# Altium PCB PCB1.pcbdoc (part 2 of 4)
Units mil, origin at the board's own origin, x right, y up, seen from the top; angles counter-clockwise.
Board outline 6180 x 7065 mil, 2 copper layers (Top Layer, Bottom Layer); 471 components, 245 nets, 1464 pads, 505 vias.
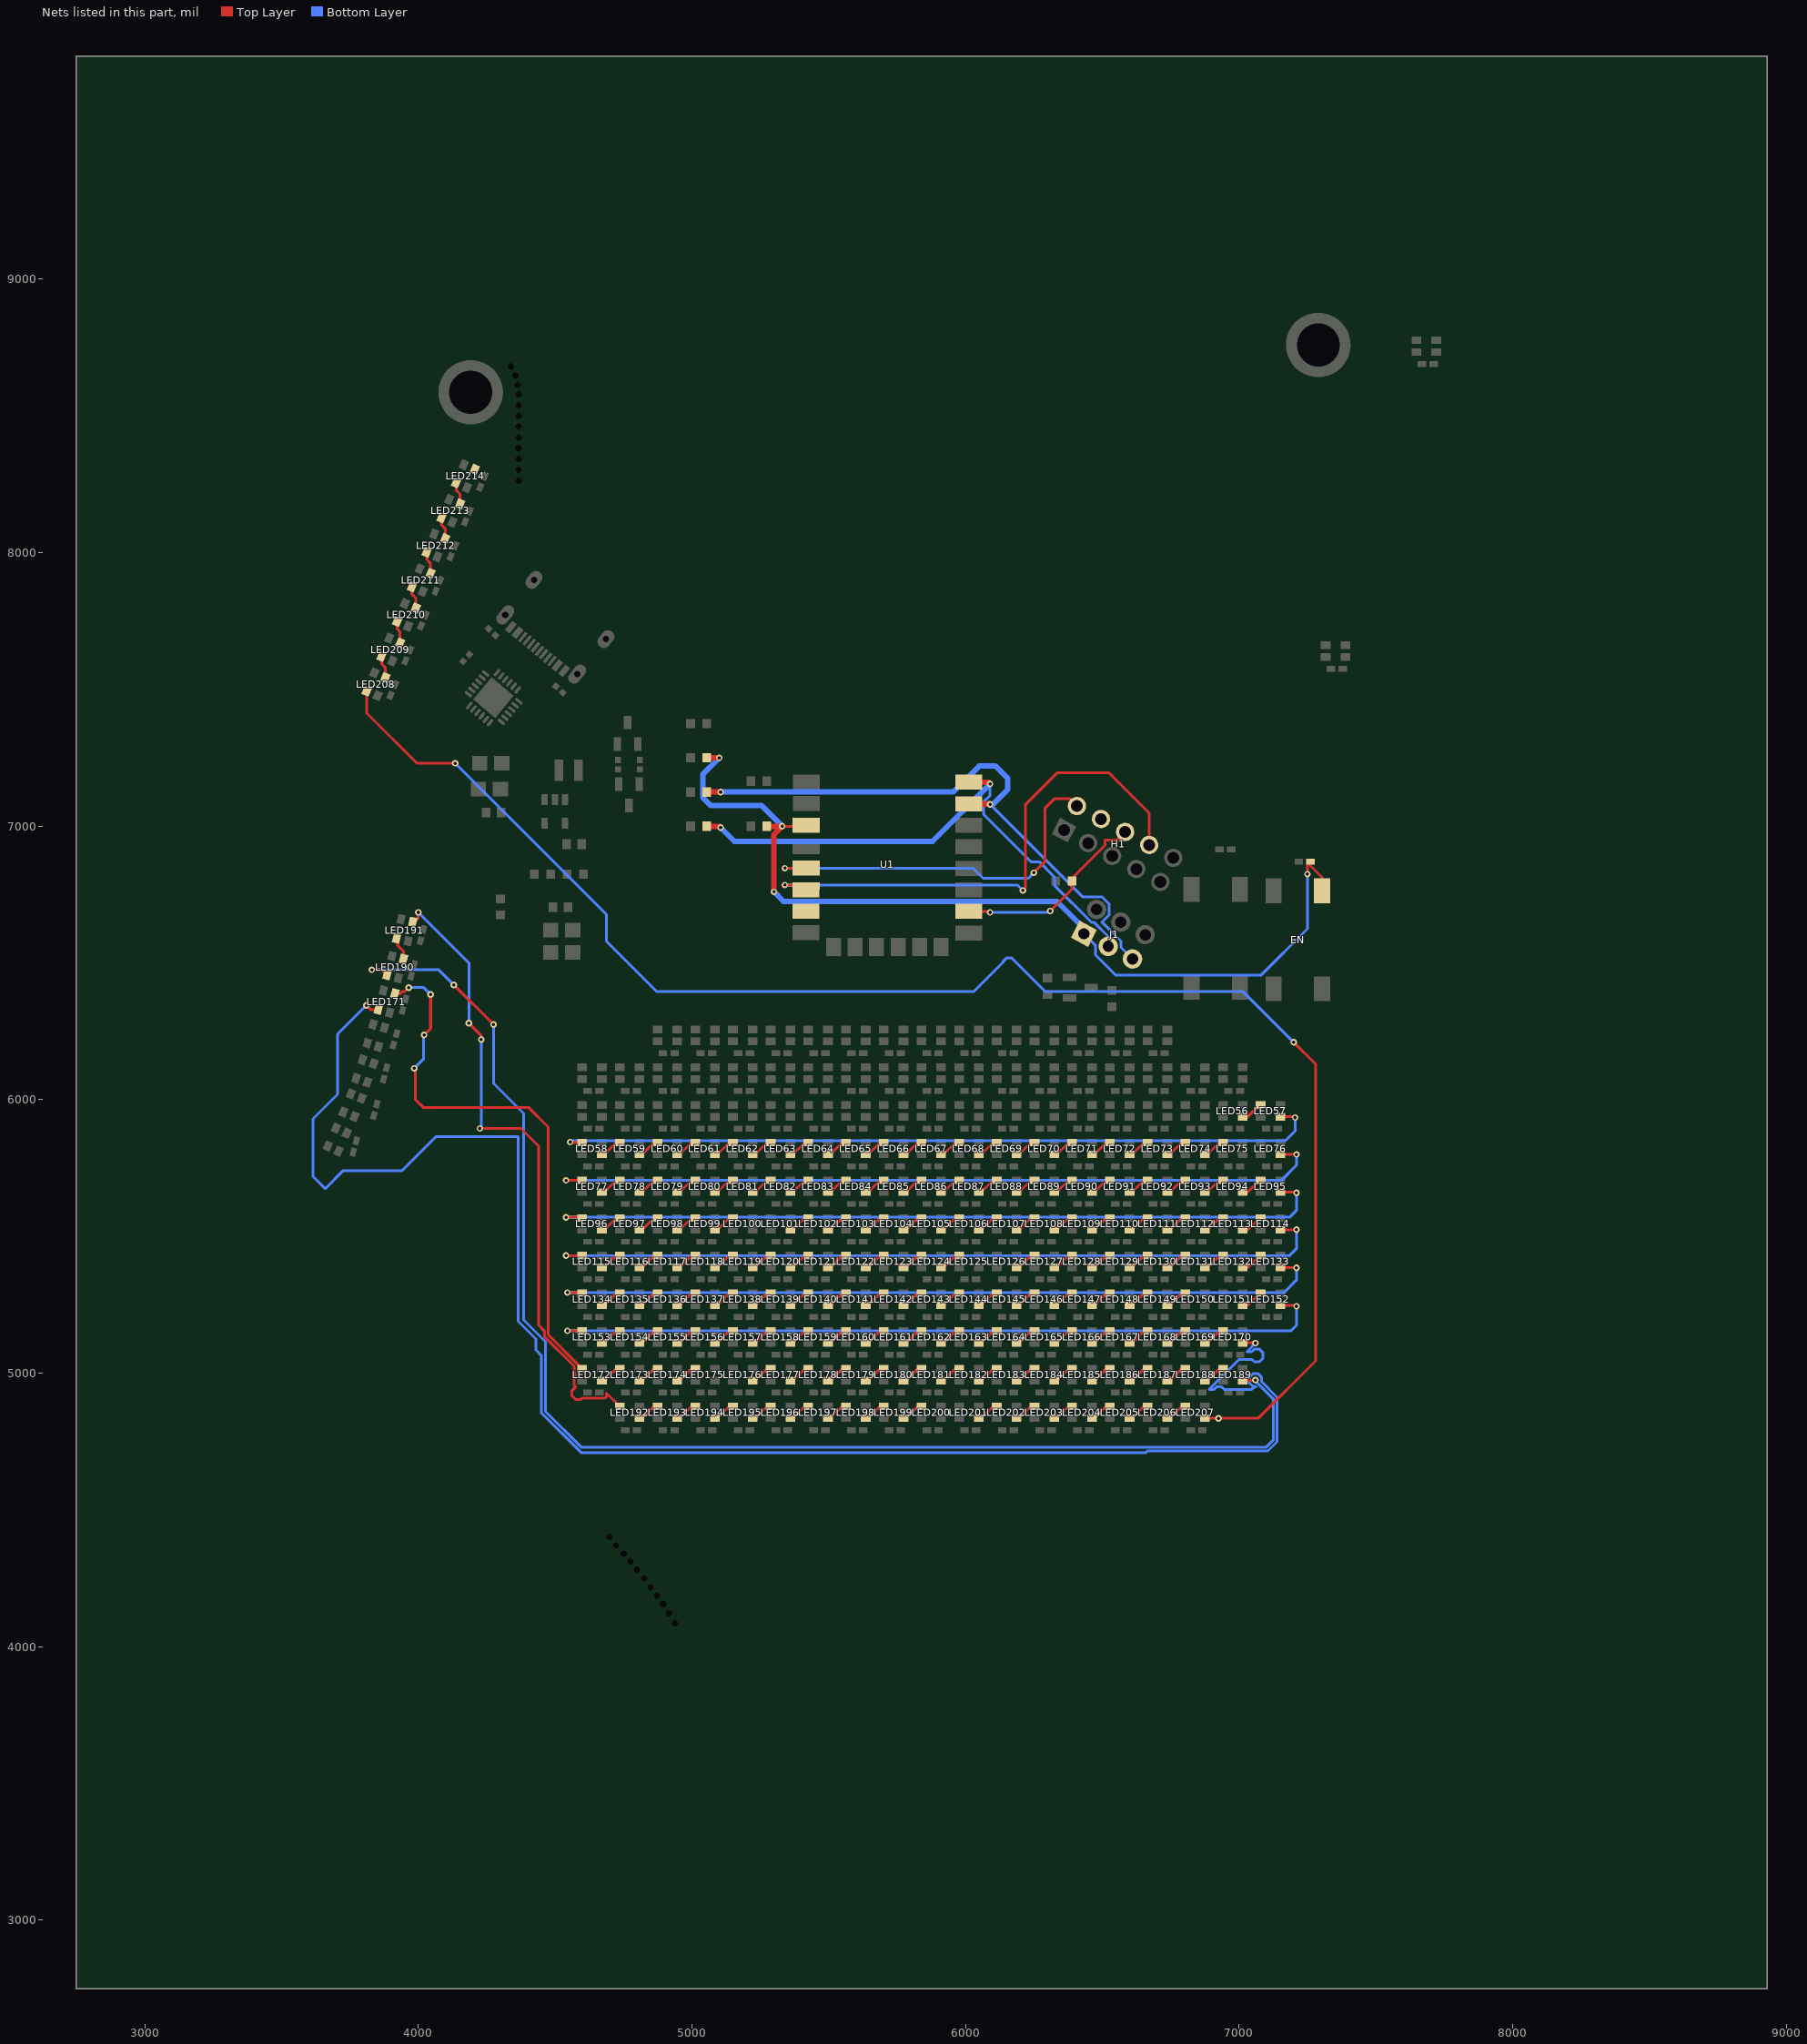
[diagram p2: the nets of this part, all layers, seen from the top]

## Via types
v1: diameter 24.02, hole 12.01, Top Layer to Bottom Layer, 504 vias
v2: diameter 23.62, hole 12.01, Top Layer to Bottom Layer, 1 vias

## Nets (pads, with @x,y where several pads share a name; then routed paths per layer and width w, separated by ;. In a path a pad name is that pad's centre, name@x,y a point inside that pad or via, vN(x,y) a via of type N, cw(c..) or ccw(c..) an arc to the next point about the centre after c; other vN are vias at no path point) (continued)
$2N20936: LED56.1 LED57.3 | length 83.7
  Top Layer w10: LED56.1@7013.54,5937.75 7032.04,5937.75 7075.35,5981.06 LED57.3@7079.29,5981.06
$2N20940: LED57.1 LED58.3 | length 2816.1
  Top Layer w10: v1(4555,5845) 4556.73,5843.27 LED58.3@4598.98,5843.27 ; LED57.1@7151.34,5937.75 7202.25,5937.75 v1(7205,5935)
  Bottom Layer w10: v1(4555,5845) 4560,5850 7170,5850 7205,5885 v1(7205,5935)
$2N20944: LED58.1 LED59.3 | length 83.7
  Top Layer w10: LED58.1@4671.02,5799.96 4680.12,5799.96 4723.43,5843.27 LED59.3@4736.77,5843.27
$2N20948: LED59.1 LED60.3 | length 83.7
  Top Layer w10: LED59.1@4808.82,5799.96 4817.91,5799.96 4861.22,5843.27 LED60.3@4874.57,5843.27
$2N20952: LED60.1 LED61.3 | length 83.7
  Top Layer w10: LED60.1@4946.62,5799.96 4955.71,5799.96 4999.02,5843.27 LED61.3@5012.36,5843.27
$2N20956: LED61.1 LED62.3 | length 83.7
  Top Layer w10: LED61.1@5084.41,5799.96 5093.5,5799.96 5136.81,5843.27 LED62.3@5150.16,5843.27
$2N20960: LED62.1 LED63.3 | length 83.7
  Top Layer w10: LED62.1@5222.21,5799.96 5231.3,5799.96 5274.61,5843.27 LED63.3@5287.95,5843.27
$2N20964: LED63.1 LED64.3 | length 83.7
  Top Layer w10: LED63.1@5360,5799.96 5369.09,5799.96 5412.4,5843.27 LED64.3@5425.75,5843.27
$2N20968: LED64.1 LED65.3 | length 83.7
  Top Layer w10: LED64.1@5497.8,5799.96 5506.89,5799.96 5550.2,5843.27 LED65.3@5563.54,5843.27
$2N20972: LED65.1 LED66.3 | length 83.7
  Top Layer w10: LED65.1@5635.59,5799.96 5644.68,5799.96 5687.99,5843.27 LED66.3@5701.34,5843.27
$2N20976: LED66.1 LED67.3 | length 83.7
  Top Layer w10: LED66.1@5773.39,5799.96 5782.48,5799.96 5825.79,5843.27 LED67.3@5839.13,5843.27
$2N20980: LED67.1 LED68.3 | length 83.7
  Top Layer w10: LED67.1@5911.18,5799.96 5920.28,5799.96 5963.59,5843.27 LED68.3@5976.93,5843.27
$2N20984: LED68.1 LED69.3 | length 83.7
  Top Layer w10: LED68.1@6048.98,5799.96 6058.07,5799.96 6101.38,5843.27 LED69.3@6114.72,5843.27
$2N20988: LED69.1 LED70.3 | length 83.7
  Top Layer w10: LED69.1@6186.77,5799.96 6195.87,5799.96 6239.18,5843.27 LED70.3@6252.52,5843.27
$2N20992: LED70.1 LED71.3 | length 83.7
  Top Layer w10: LED70.1@6324.57,5799.96 6333.66,5799.96 6376.97,5843.27 LED71.3@6390.31,5843.27
$2N20996: LED71.1 LED72.3 | length 83.7
  Top Layer w10: LED71.1@6462.36,5799.96 6471.46,5799.96 6514.77,5843.27 LED72.3@6528.11,5843.27
$2N21000: LED72.1 LED73.3 | length 83.7
  Top Layer w10: LED72.1@6600.16,5799.96 6609.25,5799.96 6652.56,5843.27 LED73.3@6665.9,5843.27
$2N21004: LED73.1 LED74.3 | length 83.7
  Top Layer w10: LED73.1@6737.95,5799.96 6747.05,5799.96 6790.36,5843.27 LED74.3@6803.7,5843.27
$2N21008: LED74.1 LED75.3 | length 83.7
  Top Layer w10: LED74.1@6875.75,5799.96 6884.84,5799.96 6928.15,5843.27 LED75.3@6941.49,5843.27
$2N21012: LED76.1 LED77.3 | length 2850.6
  Top Layer w10: v1(4540,5705) 4598.5,5705 LED77.3@4598.98,5705.47 ; LED76.1@7151.34,5799.96 v1(7210,5800)
  Bottom Layer w10: v1(4540,5705) 7155,5705 7210,5760 v1(7210,5800)
$2N21270: LED77.1 LED78.3 | length 83.7
  Top Layer w10: LED77.1@4671.02,5662.16 4680.12,5662.16 4723.43,5705.47 LED78.3@4736.77,5705.47
$2N21274: LED78.1 LED79.3 | length 83.7
  Top Layer w10: LED78.1@4808.82,5662.16 4817.91,5662.16 4861.22,5705.47 LED79.3@4874.57,5705.47
$2N21278: LED79.1 LED80.3 | length 83.7
  Top Layer w10: LED79.1@4946.62,5662.16 4955.71,5662.16 4999.02,5705.47 LED80.3@5012.36,5705.47
$2N21282: LED80.1 LED81.3 | length 83.7
  Top Layer w10: LED80.1@5084.41,5662.16 5093.5,5662.16 5136.81,5705.47 LED81.3@5150.16,5705.47
$2N21286: LED81.1 LED82.3 | length 83.7
  Top Layer w10: LED81.1@5222.21,5662.16 5231.3,5662.16 5274.61,5705.47 LED82.3@5287.95,5705.47
$2N21290: LED82.1 LED83.3 | length 83.7
  Top Layer w10: LED82.1@5360,5662.16 5369.09,5662.16 5412.4,5705.47 LED83.3@5425.75,5705.47
$2N21294: LED83.1 LED84.3 | length 83.7
  Top Layer w10: LED83.1@5497.8,5662.16 5506.89,5662.16 5550.2,5705.47 LED84.3@5563.54,5705.47
$2N21298: LED84.1 LED85.3 | length 83.7
  Top Layer w10: LED84.1@5635.59,5662.16 5644.68,5662.16 5687.99,5705.47 LED85.3@5701.34,5705.47
$2N21302: LED85.1 LED86.3 | length 83.7
  Top Layer w10: LED85.1@5773.39,5662.16 5782.48,5662.16 5825.79,5705.47 LED86.3@5839.13,5705.47
$2N21306: LED86.1 LED87.3 | length 83.7
  Top Layer w10: LED86.1@5911.18,5662.16 5920.28,5662.16 5963.59,5705.47 LED87.3@5976.93,5705.47
$2N21310: LED87.1 LED88.3 | length 83.7
  Top Layer w10: LED87.1@6048.98,5662.16 6058.07,5662.16 6101.38,5705.47 LED88.3@6114.72,5705.47
$2N21314: LED88.1 LED89.3 | length 83.7
  Top Layer w10: LED88.1@6186.77,5662.16 6195.87,5662.16 6239.18,5705.47 LED89.3@6252.52,5705.47
$2N21318: LED89.1 LED90.3 | length 83.7
  Top Layer w10: LED89.1@6324.57,5662.16 6333.66,5662.16 6376.97,5705.47 LED90.3@6390.31,5705.47
$2N21322: LED90.1 LED91.3 | length 83.7
  Top Layer w10: LED90.1@6462.36,5662.16 6471.46,5662.16 6514.77,5705.47 LED91.3@6528.11,5705.47
$2N21326: LED91.1 LED92.3 | length 83.7
  Top Layer w10: LED91.1@6600.16,5662.16 6609.25,5662.16 6652.56,5705.47 LED92.3@6665.9,5705.47
$2N21330: LED92.1 LED93.3 | length 83.7
  Top Layer w10: LED92.1@6737.95,5662.16 6747.05,5662.16 6790.36,5705.47 LED93.3@6803.7,5705.47
$2N21334: LED93.1 LED94.3 | length 83.7
  Top Layer w10: LED93.1@6875.75,5662.16 6884.84,5662.16 6928.15,5705.47 LED94.3@6941.49,5705.47
$2N21338: LED94.1 LED95.3 | length 83.7
  Top Layer w10: LED94.1@7013.54,5662.16 7032.04,5662.16 7075.35,5705.47 LED95.3@7079.29,5705.47
$2N21342: LED95.1 LED96.3 | length 2864.8
  Top Layer w10: v1(4540,5570) 4596.65,5570 LED96.3@4598.98,5567.68 ; LED95.1@7151.34,5662.16 7207.84,5662.16 v1(7210,5660)
  Bottom Layer w10: v1(4540,5570) 7185,5570 7210,5595 v1(7210,5660)
$2N21346: LED96.1 LED97.3 | length 83.7
  Top Layer w10: LED96.1@4671.02,5524.37 4680.12,5524.37 4723.43,5567.68 LED97.3@4736.77,5567.68
$2N21350: LED97.1 LED98.3 | length 83.7
  Top Layer w10: LED97.1@4808.82,5524.37 4817.91,5524.37 4861.22,5567.68 LED98.3@4874.57,5567.68
$2N21354: LED98.1 LED99.3 | length 83.7
  Top Layer w10: LED98.1@4946.62,5524.37 4955.71,5524.37 4999.02,5567.68 LED99.3@5012.36,5567.68
$2N21358: LED99.1 LED100.3 | length 83.7
  Top Layer w10: LED99.1@5084.41,5524.37 5093.5,5524.37 5136.81,5567.68 LED100.3@5150.16,5567.68
$2N21362: LED101.1 LED102.3 | length 83.7
  Top Layer w10: LED101.1@5360,5524.37 5369.09,5524.37 5412.4,5567.68 LED102.3@5425.75,5567.68
$2N21620: LED102.1 LED103.3 | length 83.7
  Top Layer w10: LED102.1@5497.8,5524.37 5506.89,5524.37 5550.2,5567.68 LED103.3@5563.54,5567.68
$2N21624: LED103.1 LED104.3 | length 83.7
  Top Layer w10: LED103.1@5635.59,5524.37 5644.68,5524.37 5687.99,5567.68 LED104.3@5701.34,5567.68
$2N21628: LED104.1 LED105.3 | length 83.7
  Top Layer w10: LED104.1@5773.39,5524.37 5782.48,5524.37 5825.79,5567.68 LED105.3@5839.13,5567.68
$2N21632: LED105.1 LED106.3 | length 83.7
  Top Layer w10: LED105.1@5911.18,5524.37 5920.28,5524.37 5963.59,5567.68 LED106.3@5976.93,5567.68
$2N21636: LED106.1 LED107.3 | length 83.7
  Top Layer w10: LED106.1@6048.98,5524.37 6058.07,5524.37 6101.38,5567.68 LED107.3@6114.72,5567.68
$2N21640: LED107.1 LED108.3 | length 83.7
  Top Layer w10: LED107.1@6186.77,5524.37 6195.87,5524.37 6239.18,5567.68 LED108.3@6252.52,5567.68
$2N21644: LED108.1 LED109.3 | length 83.7
  Top Layer w10: LED108.1@6324.57,5524.37 6333.66,5524.37 6376.97,5567.68 LED109.3@6390.31,5567.68
$2N21648: LED109.1 LED110.3 | length 83.7
  Top Layer w10: LED109.1@6462.36,5524.37 6471.46,5524.37 6514.77,5567.68 LED110.3@6528.11,5567.68
$2N21652: LED110.1 LED111.3 | length 83.7
  Top Layer w10: LED110.1@6600.16,5524.37 6609.25,5524.37 6652.56,5567.68 LED111.3@6665.9,5567.68
$2N21656: LED111.1 LED112.3 | length 83.7
  Top Layer w10: LED111.1@6737.95,5524.37 6747.05,5524.37 6790.36,5567.68 LED112.3@6803.7,5567.68
$2N21660: LED112.1 LED113.3 | length 83.7
  Top Layer w10: LED112.1@6875.75,5524.37 6884.84,5524.37 6928.15,5567.68 LED113.3@6941.49,5567.68
$2N21664: LED113.1 LED114.3 | length 83.7
  Top Layer w10: LED113.1@7013.54,5524.37 7032.04,5524.37 7075.35,5567.68 LED114.3@7079.29,5567.68
$2N21668: LED114.1 LED115.3 | length 2868.3
  Top Layer w10: v1(4540,5430) 4598.86,5430 LED115.3@4598.98,5429.88 ; LED114.1@7151.34,5524.37 7209.37,5524.37 v1(7210,5525)
  Bottom Layer w10: v1(4540,5430) 7185,5430 7210,5455 v1(7210,5525)
$2N21672: LED115.1 LED116.3 | length 83.7
  Top Layer w10: LED115.1@4671.02,5386.57 4680.12,5386.57 4723.43,5429.88 LED116.3@4736.77,5429.88
$2N21676: LED116.1 LED117.3 | length 83.7
  Top Layer w10: LED116.1@4808.82,5386.57 4817.91,5386.57 4861.22,5429.88 LED117.3@4874.57,5429.88
$2N21680: LED117.1 LED118.3 | length 83.7
  Top Layer w10: LED117.1@4946.62,5386.57 4955.71,5386.57 4999.02,5429.88 LED118.3@5012.36,5429.88
$2N21684: LED118.1 LED119.3 | length 83.7
  Top Layer w10: LED118.1@5084.41,5386.57 5093.5,5386.57 5136.81,5429.88 LED119.3@5150.16,5429.88
$2N21688: LED119.1 LED120.3 | length 83.7
  Top Layer w10: LED119.1@5222.21,5386.57 5231.3,5386.57 5274.61,5429.88 LED120.3@5287.95,5429.88
$2N21692: LED120.1 LED121.3 | length 83.7
  Top Layer w10: LED120.1@5360,5386.57 5369.09,5386.57 5412.4,5429.88 LED121.3@5425.75,5429.88
$2N21696: LED121.1 LED122.3 | length 83.7
  Top Layer w10: LED121.1@5497.8,5386.57 5506.89,5386.57 5550.2,5429.88 LED122.3@5563.54,5429.88
$2N21700: LED122.1 LED123.3 | length 83.7
  Top Layer w10: LED122.1@5635.59,5386.57 5644.68,5386.57 5687.99,5429.88 LED123.3@5701.34,5429.88
$2N21704: LED123.1 LED124.3 | length 83.7
  Top Layer w10: LED123.1@5773.39,5386.57 5782.48,5386.57 5825.79,5429.88 LED124.3@5839.13,5429.88
$2N21708: LED124.1 LED125.3 | length 83.7
  Top Layer w10: LED124.1@5911.18,5386.57 5920.28,5386.57 5963.59,5429.88 LED125.3@5976.93,5429.88
$2N21712: LED126.1 LED127.3 | length 83.7
  Top Layer w10: LED126.1@6186.77,5386.57 6195.87,5386.57 6239.18,5429.88 LED127.3@6252.52,5429.88
$2N21970: LED127.1 LED128.3 | length 83.7
  Top Layer w10: LED127.1@6324.57,5386.57 6333.66,5386.57 6376.97,5429.88 LED128.3@6390.31,5429.88
$2N21974: LED128.1 LED129.3 | length 83.7
  Top Layer w10: LED128.1@6462.36,5386.57 6471.46,5386.57 6514.77,5429.88 LED129.3@6528.11,5429.88
$2N21978: LED129.1 LED130.3 | length 83.7
  Top Layer w10: LED129.1@6600.16,5386.57 6609.25,5386.57 6652.56,5429.88 LED130.3@6665.9,5429.88
$2N21982: LED130.1 LED131.3 | length 83.7
  Top Layer w10: LED130.1@6737.95,5386.57 6747.05,5386.57 6790.36,5429.88 LED131.3@6803.7,5429.88
$2N21986: LED131.1 LED132.3 | length 83.7
  Top Layer w10: LED131.1@6875.75,5386.57 6884.84,5386.57 6928.15,5429.88 LED132.3@6941.49,5429.88
$2N21990: LED132.1 LED133.3 | length 83.7
  Top Layer w10: LED132.1@7013.54,5386.57 7032.04,5386.57 7075.35,5429.88 LED133.3@7079.29,5429.88
$2N21994: LED133.1 LED134.3 | length 2843.1
  Top Layer w10: v1(4545,5295) 4596.06,5295 LED134.3@4598.98,5292.09 ; LED133.1@7151.34,5386.57 7208.43,5386.57 v1(7210,5385)
  Bottom Layer w10: v1(4545,5295) 7165,5295 7210,5340 v1(7210,5385)
$2N21998: LED134.1 LED135.3 | length 83.7
  Top Layer w10: LED134.1@4671.02,5248.78 4680.12,5248.78 4723.43,5292.09 LED135.3@4736.77,5292.09
$2N22002: LED135.1 LED136.3 | length 83.7
  Top Layer w10: LED135.1@4808.82,5248.78 4817.91,5248.78 4861.22,5292.09 LED136.3@4874.57,5292.09
$2N22006: LED136.1 LED137.3 | length 83.7
  Top Layer w10: LED136.1@4946.62,5248.78 4955.71,5248.78 4999.02,5292.09 LED137.3@5012.36,5292.09
$2N22010: LED137.1 LED138.3 | length 83.7
  Top Layer w10: LED137.1@5084.41,5248.78 5093.5,5248.78 5136.81,5292.09 LED138.3@5150.16,5292.09
$2N22014: LED138.1 LED139.3 | length 83.7
  Top Layer w10: LED138.1@5222.21,5248.78 5231.3,5248.78 5274.61,5292.09 LED139.3@5287.95,5292.09
$2N22018: LED139.1 LED140.3 | length 83.7
  Top Layer w10: LED139.1@5360,5248.78 5369.09,5248.78 5412.4,5292.09 LED140.3@5425.75,5292.09
$2N22022: LED140.1 LED141.3 | length 83.7
  Top Layer w10: LED140.1@5497.8,5248.78 5506.89,5248.78 5550.2,5292.09 LED141.3@5563.54,5292.09
$2N22026: LED141.1 LED142.3 | length 83.7
  Top Layer w10: LED141.1@5635.59,5248.78 5644.68,5248.78 5687.99,5292.09 LED142.3@5701.34,5292.09
$2N22030: LED142.1 LED143.3 | length 83.7
  Top Layer w10: LED142.1@5773.39,5248.78 5782.48,5248.78 5825.79,5292.09 LED143.3@5839.13,5292.09
$2N22034: LED143.1 LED144.3 | length 83.7
  Top Layer w10: LED143.1@5911.18,5248.78 5920.28,5248.78 5963.59,5292.09 LED144.3@5976.93,5292.09
$2N22038: LED144.1 LED145.3 | length 83.7
  Top Layer w10: LED144.1@6048.98,5248.78 6058.07,5248.78 6101.38,5292.09 LED145.3@6114.72,5292.09
$2N22042: LED145.1 LED146.3 | length 83.7
  Top Layer w10: LED145.1@6186.77,5248.78 6195.87,5248.78 6239.18,5292.09 LED146.3@6252.52,5292.09
$2N22046: LED146.1 LED147.3 | length 83.7
  Top Layer w10: LED146.1@6324.57,5248.78 6333.66,5248.78 6376.97,5292.09 LED147.3@6390.31,5292.09
$2N22050: LED147.1 LED148.3 | length 83.7
  Top Layer w10: LED147.1@6462.36,5248.78 6471.46,5248.78 6514.77,5292.09 LED148.3@6528.11,5292.09
$2N22054: LED148.1 LED149.3 | length 83.7
  Top Layer w10: LED148.1@6600.16,5248.78 6609.25,5248.78 6652.56,5292.09 LED149.3@6665.9,5292.09
$2N22058: LED149.1 LED150.3 | length 83.7
  Top Layer w10: LED149.1@6737.95,5248.78 6747.05,5248.78 6790.36,5292.09 LED150.3@6803.7,5292.09
$2N22062: LED151.1 LED152.3 | length 83.7
  Top Layer w10: LED151.1@7013.54,5248.78 7032.04,5248.78 7075.35,5292.09 LED152.3@7079.29,5292.09
$2N22320: LED152.1 LED153.3 | length 2857.8
  Top Layer w10: v1(4545,5155) 4598.27,5155 LED153.3@4598.98,5154.29 ; LED152.1@7151.34,5248.78 7206.22,5248.78 v1(7210,5245)
  Bottom Layer w10: v1(4545,5155) 7190,5155 7210,5175 v1(7210,5245)
$2N22324: LED153.1 LED154.3 | length 83.7
  Top Layer w10: LED153.1@4671.02,5110.98 4680.12,5110.98 4723.43,5154.29 LED154.3@4736.77,5154.29
$2N22328: LED154.1 LED155.3 | length 83.7
  Top Layer w10: LED154.1@4808.82,5110.98 4817.91,5110.98 4861.22,5154.29 LED155.3@4874.57,5154.29
$2N22332: LED155.1 LED156.3 | length 83.7
  Top Layer w10: LED155.1@4946.62,5110.98 4955.71,5110.98 4999.02,5154.29 LED156.3@5012.36,5154.29
$2N22336: LED156.1 LED157.3 | length 83.7
  Top Layer w10: LED156.1@5084.41,5110.98 5093.5,5110.98 5136.81,5154.29 LED157.3@5150.16,5154.29
$2N22340: LED157.1 LED158.3 | length 83.7
  Top Layer w10: LED157.1@5222.21,5110.98 5231.3,5110.98 5274.61,5154.29 LED158.3@5287.95,5154.29
$2N22344: LED158.1 LED159.3 | length 83.7
  Top Layer w10: LED158.1@5360,5110.98 5369.09,5110.98 5412.4,5154.29 LED159.3@5425.75,5154.29
$2N22348: LED159.1 LED160.3 | length 83.7
  Top Layer w10: LED159.1@5497.8,5110.98 5506.89,5110.98 5550.2,5154.29 LED160.3@5563.54,5154.29
$2N22352: LED160.1 LED161.3 | length 83.7
  Top Layer w10: LED160.1@5635.59,5110.98 5644.68,5110.98 5687.99,5154.29 LED161.3@5701.34,5154.29
$2N22356: LED161.1 LED162.3 | length 83.7
  Top Layer w10: LED161.1@5773.39,5110.98 5782.48,5110.98 5825.79,5154.29 LED162.3@5839.13,5154.29
$2N22360: LED162.1 LED163.3 | length 83.7
  Top Layer w10: LED162.1@5911.18,5110.98 5920.28,5110.98 5963.59,5154.29 LED163.3@5976.93,5154.29
$2N22364: LED163.1 LED164.3 | length 83.7
  Top Layer w10: LED163.1@6048.98,5110.98 6058.07,5110.98 6101.38,5154.29 LED164.3@6114.72,5154.29
$2N22368: LED164.1 LED165.3 | length 83.7
  Top Layer w10: LED164.1@6186.77,5110.98 6195.87,5110.98 6239.18,5154.29 LED165.3@6252.52,5154.29
$2N22372: LED165.1 LED166.3 | length 83.7
  Top Layer w10: LED165.1@6324.57,5110.98 6333.66,5110.98 6376.97,5154.29 LED166.3@6390.31,5154.29
$2N22376: LED166.1 LED167.3 | length 83.7
  Top Layer w10: LED166.1@6462.36,5110.98 6471.46,5110.98 6514.77,5154.29 LED167.3@6528.11,5154.29
$2N22380: LED167.1 LED168.3 | length 83.7
  Top Layer w10: LED167.1@6600.16,5110.98 6609.25,5110.98 6652.56,5154.29 LED168.3@6665.9,5154.29
$2N22384: LED168.1 LED169.3 | length 83.7
  Top Layer w10: LED168.1@6737.95,5110.98 6747.05,5110.98 6790.36,5154.29 LED169.3@6803.7,5154.29
$2N22388: LED169.1 LED170.3 | length 83.7
  Top Layer w10: LED169.1@6875.75,5110.98 6884.84,5110.98 6928.15,5154.29 LED170.3@6941.49,5154.29
$2N22392: LED170.1 LED171.3 | length 6392
  Top Layer w10: v1(3810,6345) 3825.39,6329.61 LED171.3@3853.86,6329.61 ; LED170.1@7013.54,5110.98 7059.02,5110.98 v1(7060,5110)
  Bottom Layer w10: v1(3810,6345) 3705,6240 3705,6020 3615,5930 3615,5720 3660,5675 3725.98,5740.98 3940.81,5740.98 4064.82,5865 4365,5865 4365,5190 4430,5125 4430,5085 4449.55,5065.45 4449.55,4855.45 4595,4710 6660,4710 6665.98,4715.98 7105.81,4715.98 7139.02,4749.19 7139.02,4912.51 7082.99,4968.54 7082.99,4984.52 7069.52,4997.99 7050.48,4997.99 7037.01,4984.52 7037.01,4965.48 7050.48,4952.01 7059.88,4952.01 7061.85,4950.04 7055.55,4950.04 7046.57,4941.06 6945.78,4941.06 6936.8,4950.04 6917.75,4950.04 6908.78,4941.06 6891.06,4941.06 7000.83,5050.83 7046.57,5050.83 7055.55,5041.85 7074.6,5041.85 7088.07,5055.32 7088.07,5074.37 7074.6,5087.83 7055.55,5087.83 7046.57,5078.86 7028.86,5078.86 v1(7060,5110)
$2N22396: LED171.1 LED172.3 | length 2021.5
  Top Layer w10: LED171.1@3914.34,6388 3934.63,6388 3942.94,6396.31 3951.31,6396.31 v1(3965,6410) ; v1(3985,6115) 3990,6110 3990,6000 4017.99,5972.01 4402.99,5972.01 4475,5900 4475,5140.47 LED172.3@4598.98,5016.5 ; v1(4021.09,6236.42) 4045,6260.32 v1(4045,6385)
  Bottom Layer w10: v1(3965,6410) 4020,6410 v1(4045,6385) ; v1(3985,6115) 4020,6150 v1@4020,6235
$2N22400: LED172.1 LED173.3 | length 83.7
  Top Layer w10: LED172.1@4671.02,4973.19 4680.12,4973.19 4723.43,5016.5 LED173.3@4736.77,5016.5
$2N22404: LED173.1 LED174.3 | length 83.7
  Top Layer w10: LED173.1@4808.82,4973.19 4817.91,4973.19 4861.22,5016.5 LED174.3@4874.57,5016.5
$2N22408: LED174.1 LED175.3 | length 83.7
  Top Layer w10: LED174.1@4946.62,4973.19 4955.71,4973.19 4999.02,5016.5 LED175.3@5012.36,5016.5
$2N22412: LED176.1 LED177.3 | length 83.7
  Top Layer w10: LED176.1@5222.21,4973.19 5231.3,4973.19 5274.61,5016.5 LED177.3@5287.95,5016.5
$2N22670: LED177.1 LED178.3 | length 83.7
  Top Layer w10: LED177.1@5360,4973.19 5369.09,4973.19 5412.4,5016.5 LED178.3@5425.75,5016.5
$2N22674: LED178.1 LED179.3 | length 83.7
  Top Layer w10: LED178.1@5497.8,4973.19 5506.89,4973.19 5550.2,5016.5 LED179.3@5563.54,5016.5
$2N22678: LED179.1 LED180.3 | length 83.7
  Top Layer w10: LED179.1@5635.59,4973.19 5644.68,4973.19 5687.99,5016.5 LED180.3@5701.34,5016.5
$2N22682: LED180.1 LED181.3 | length 83.7
  Top Layer w10: LED180.1@5773.39,4973.19 5782.48,4973.19 5825.79,5016.5 LED181.3@5839.13,5016.5
$2N22686: LED181.1 LED182.3 | length 83.7
  Top Layer w10: LED181.1@5911.18,4973.19 5920.28,4973.19 5963.59,5016.5 LED182.3@5976.93,5016.5
$2N22690: LED182.1 LED183.3 | length 83.7
  Top Layer w10: LED182.1@6048.98,4973.19 6058.07,4973.19 6101.38,5016.5 LED183.3@6114.72,5016.5
$2N22694: LED183.1 LED184.3 | length 83.7
  Top Layer w10: LED183.1@6186.77,4973.19 6195.87,4973.19 6239.18,5016.5 LED184.3@6252.52,5016.5
$2N22698: LED184.1 LED185.3 | length 83.7
  Top Layer w10: LED184.1@6324.57,4973.19 6333.66,4973.19 6376.97,5016.5 LED185.3@6390.31,5016.5
$2N22702: LED185.1 LED186.3 | length 83.7
  Top Layer w10: LED185.1@6462.36,4973.19 6471.46,4973.19 6514.77,5016.5 LED186.3@6528.11,5016.5
$2N22706: LED186.1 LED187.3 | length 83.7
  Top Layer w10: LED186.1@6600.16,4973.19 6609.25,4973.19 6652.56,5016.5 LED187.3@6665.9,5016.5
$2N22710: LED187.1 LED188.3 | length 83.7
  Top Layer w10: LED187.1@6737.95,4973.19 6747.05,4973.19 6790.36,5016.5 LED188.3@6803.7,5016.5
$2N22714: LED188.1 LED189.3 | length 83.7
  Top Layer w10: LED188.1@6875.75,4973.19 6884.84,4973.19 6928.15,5016.5 LED189.3@6941.49,5016.5
$2N22718: LED189.1 LED190.3 | length 5103.2
  Top Layer w10: v1(3830,6475) 3866.12,6475 LED190.3@3885.36,6455.76 ; v1(4130,6420) v1(4275,6275) ; LED189.1@7013.54,4973.19 7058.19,4973.19 v1(7060,4975)
  Bottom Layer w10: v1(3830,6475) 4075,6475 v1(4130,6420) ; v1(4275,6275) 4275,6060 4385,5950 4385,5195 4465,5115 4465,4860 4595,4730 7100,4730 7125,4755 7125,4906.71 7060,4971.71 v1(7060,4975)
$2N22722: LED190.1 LED191.3 | length 84.8
  Top Layer w10: LED191.3@3924.21,6589.96 3924.21,6564.28 3945.84,6542.65 LED190.1@3945.84,6514.15
$2N22726: LED191.1 LED192.3 | length 2368.1
  Top Layer w10: LED191.1@3984.68,6648.35 4000,6663.67 v1(4000,6685) ; v1(4185,6280) 4230,6235 v1(4230,6220) ; v1(4225,5895) 4375,5895 4440,5830 4440,5175.47 4460.98,5154.49 4460.98,5134.67 4570.27,5025.38 4570.27,4998.17 4573.6,4994.84 4570.27,4991.52 4570.27,4954.86 4575.16,4949.97 4561.77,4936.57 4561.77,4917.52 4575.23,4904.06 4594.28,4904.06 4598.46,4908.23 4638.64,4908.23 4640,4909.59 4641.36,4908.23 4681.56,4908.23 4688,4914.66 4688,4927.48 LED192.3@4736.77,4878.7
  Bottom Layer w10: v1(4000,6685) 4185,6500 v1(4185,6280) ; v1(4225,5895) 4230,5900 v1(4230,6220)
$2N22730: LED192.1 LED193.3 | length 83.7
  Top Layer w10: LED192.1@4808.82,4835.39 4817.91,4835.39 4861.22,4878.7 LED193.3@4874.57,4878.7
$2N22734: LED193.1 LED194.3 | length 83.7
  Top Layer w10: LED193.1@4946.62,4835.39 4955.71,4835.39 4999.02,4878.7 LED194.3@5012.36,4878.7
$2N22738: LED194.1 LED195.3 | length 83.7
  Top Layer w10: LED194.1@5084.41,4835.39 5093.5,4835.39 5136.81,4878.7 LED195.3@5150.16,4878.7
$2N22742: LED195.1 LED196.3 | length 83.7
  Top Layer w10: LED195.1@5222.21,4835.39 5231.3,4835.39 5274.61,4878.7 LED196.3@5287.95,4878.7
$2N22746: LED196.1 LED197.3 | length 83.7
  Top Layer w10: LED196.1@5360,4835.39 5369.09,4835.39 5412.4,4878.7 LED197.3@5425.75,4878.7
$2N22750: LED197.1 LED198.3 | length 83.7
  Top Layer w10: LED197.1@5497.8,4835.39 5506.89,4835.39 5550.2,4878.7 LED198.3@5563.54,4878.7
$2N22754: LED198.1 LED199.3 | length 83.7
  Top Layer w10: LED198.1@5635.59,4835.39 5644.68,4835.39 5687.99,4878.7 LED199.3@5701.34,4878.7
$2N22758: LED199.1 LED200.3 | length 83.7
  Top Layer w10: LED199.1@5773.39,4835.39 5782.48,4835.39 5825.79,4878.7 LED200.3@5839.13,4878.7
$2N22762: LED201.1 LED202.3 | length 83.7
  Top Layer w10: LED201.1@6048.98,4835.39 6058.07,4835.39 6101.38,4878.7 LED202.3@6114.72,4878.7
$2N23020: LED202.1 LED203.3 | length 83.7
  Top Layer w10: LED202.1@6186.77,4835.39 6195.87,4835.39 6239.18,4878.7 LED203.3@6252.52,4878.7
$2N23024: LED203.1 LED204.3 | length 83.7
  Top Layer w10: LED203.1@6324.57,4835.39 6333.66,4835.39 6376.97,4878.7 LED204.3@6390.31,4878.7
$2N23028: LED204.1 LED205.3 | length 83.7
  Top Layer w10: LED204.1@6462.36,4835.39 6471.46,4835.39 6514.77,4878.7 LED205.3@6528.11,4878.7
$2N23032: LED205.1 LED206.3 | length 83.7
  Top Layer w10: LED205.1@6600.16,4835.39 6609.25,4835.39 6652.56,4878.7 LED206.3@6665.9,4878.7
$2N23036: LED206.1 LED207.3 | length 83.7
  Top Layer w10: LED206.1@6737.95,4835.39 6747.05,4835.39 6790.36,4878.7 LED207.3@6803.7,4878.7
$2N23040: LED207.1 LED208.3 | length 5817.6
  Top Layer w10: LED208.3@3811.51,7494.12 3811.51,7413.49 3995,7230 v1(4135,7230) ; LED207.1@6875.75,4835.39 6924.61,4835.39 v1(6925,4835) 7070,4835 7280,5045 7280,6130 v1(7200,6210)
  Bottom Layer w10: v1(4135,7230) 4687.01,6677.99 4687.01,6580.48 4872.48,6395 6030,6395 6137.01,6502.01 6137.01,6504.52 6150.48,6517.99 6169.52,6517.99 6292.52,6395 7015,6395 v1(7200,6210)
$2N23044: LED208.1 LED209.3 | length 83.3
  Top Layer w10: LED209.3@3865.44,7620.92 3865.44,7594.22 3879.56,7580.1 LED208.1@3879.56,7543.46
$2N23048: LED209.1 LED210.3 | length 82.6
  Top Layer w10: LED210.3@3922.69,7748.36 3922.69,7721.66 3933.5,7710.86 LED209.1@3933.5,7670.26
$2N23052: LED210.1 LED211.3 | length 83.3
  Top Layer w10: LED211.3@3976.63,7875.16 3976.63,7848.47 3990.75,7834.35 LED210.1@3990.75,7797.71
$2N23056: LED211.1 LED212.3 | length 83.3
  Top Layer w10: LED212.3@4030.57,8001.96 4030.57,7975.27 4044.69,7961.15 LED211.1@4044.69,7924.51
$2N23060: LED212.1 LED213.3 | length 83.3
  Top Layer w10: LED213.3@4084.5,8128.76 4084.5,8102.07 4098.62,8087.95 LED212.1@4098.62,8051.31
$2N23064: LED213.1 LED214.3 | length 83.3
  Top Layer w10: LED214.3@4138.44,8255.56 4138.44,8228.87 4152.56,8214.75 LED213.1@4152.56,8178.11
$2N23068: LED214.1
ESP_EN: C227.1 EN.4 J1.1 R11.1 R19.1 U1.3 | length 3515.7
  Top Layer w10: v1(5330,7000) 5413.8,7000 U1.3@5417.87,7004.07 ; v1(7250,6825) 7250,6866.46 7303.59,6812.88 EN.4@7303.59,6764.13
  Top Layer w20: R11.1@5054.66,7250 v1(5100,7250) ; v1(5300,6760) 5300,6970 v1(5330,7000) ; v1(5330,7000) 5330,6999.9 5276.5,6999.9 5276.5,7000 v1(5330,7000)
  Bottom Layer w10: J1.1@6433.21,6606.77 6475.52,6564.47 6475.52,6529.48 6550,6455 7080,6455 7250,6625 v1(7250,6825)
  Bottom Layer w20: v1(5100,7250) 5040,7190 5040,7105 5070,7075 5255,7075 v1(5330,7000) ; v1(5300,6760) 5335,6725 6334.99,6725 J1.1@6428.21,6631.77
ESP_RX: J1.5 R10.1 U1.15 | length 2290.6
  Top Layer w20: R10.1@5054.66,7125 v1(5105,7125) ; U1.15@6012.52,7080 v1(6090,7080) 6090,7082.12 U1.15@6012.52,7082.12 U1.15@6012.52,7080
  Bottom Layer w10: v1(6090,7080) 6428.09,6741.91 6498.57,6741.91 6525.76,6714.72 6525.76,6676.27 6498.57,6649.08 6499.14,6649.08 6568.35,6579.87 6568.35,6556.81 J1.5@6610.65,6514.5
  Bottom Layer w20: v1(5105,7125) 5955,7125 6050,7220 6110,7220 6155,7175 6155,7135 6100,7080 v1(6090,7080)
ESP_TCK: H1.4
ESP_TDI: H1.8 U1.6 | length 1958.9
  Top Layer w10: v1(5340,6785) 5400.44,6785 U1.6@5417.59,6767.85 ; v1(6210,6765) 6220,6775 6220,7080 6335,7195 6525,7195 6671.75,7048.25 H1.8@6671.75,6931.61
  Bottom Layer w10: v1(5340,6785) 6190,6785 v1(6210,6765)
ESP_TDO: H1.6 R3.2 U1.10 | length 730
  Top Layer w10: U1.10@6012.05,6688.42 6086.58,6688.42 v1(6090,6685) ; v1(6310,6690) 6389.66,6769.66 R3.2@6389.66,6800 6389.66,6809.66 6510,6930 6510,6950 6554.68,6950 H1.6@6583.7,6979.02
  Bottom Layer w10: v1(6090,6685) 6305,6685 v1(6310,6690)
ESP_TMS: H1.2 U1.5 | length 1405.6
  Top Layer w10: v1(5340,6846.59) U1.5@5417.68,6846.59 ; v1(6250,6830) 6290,6870 6290,7065 6325,7100 6381.45,7100 H1.2@6407.61,7073.84
  Bottom Layer w10: v1(5340,6846.59) 6028.41,6846.59 6065,6810 6230,6810 v1(6250,6830)
ESP_TX: J1.3 R9.1 U1.16 | length 2040.7
  Top Layer w20: R9.1@5054.66,7000 5100,7000 v1(5105,6995) ; U1.16@6012.62,7160.86 6084.14,7160.86 v1(6090,7155)
  Bottom Layer w10: v1(6090,7155) 6090,7112.52 6067.01,7089.52 6067.01,7042.19 6239.2,6870 6270,6870 6325,6815 6325,6784.2 6460.12,6649.08 6469.31,6649.08 6521.93,6596.46 J1.3@6521.93,6560.64
  Bottom Layer w20: v1(5105,6995) 5155,6945 5880,6945 v1(6090,7155)
ESPTCK: U1.7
